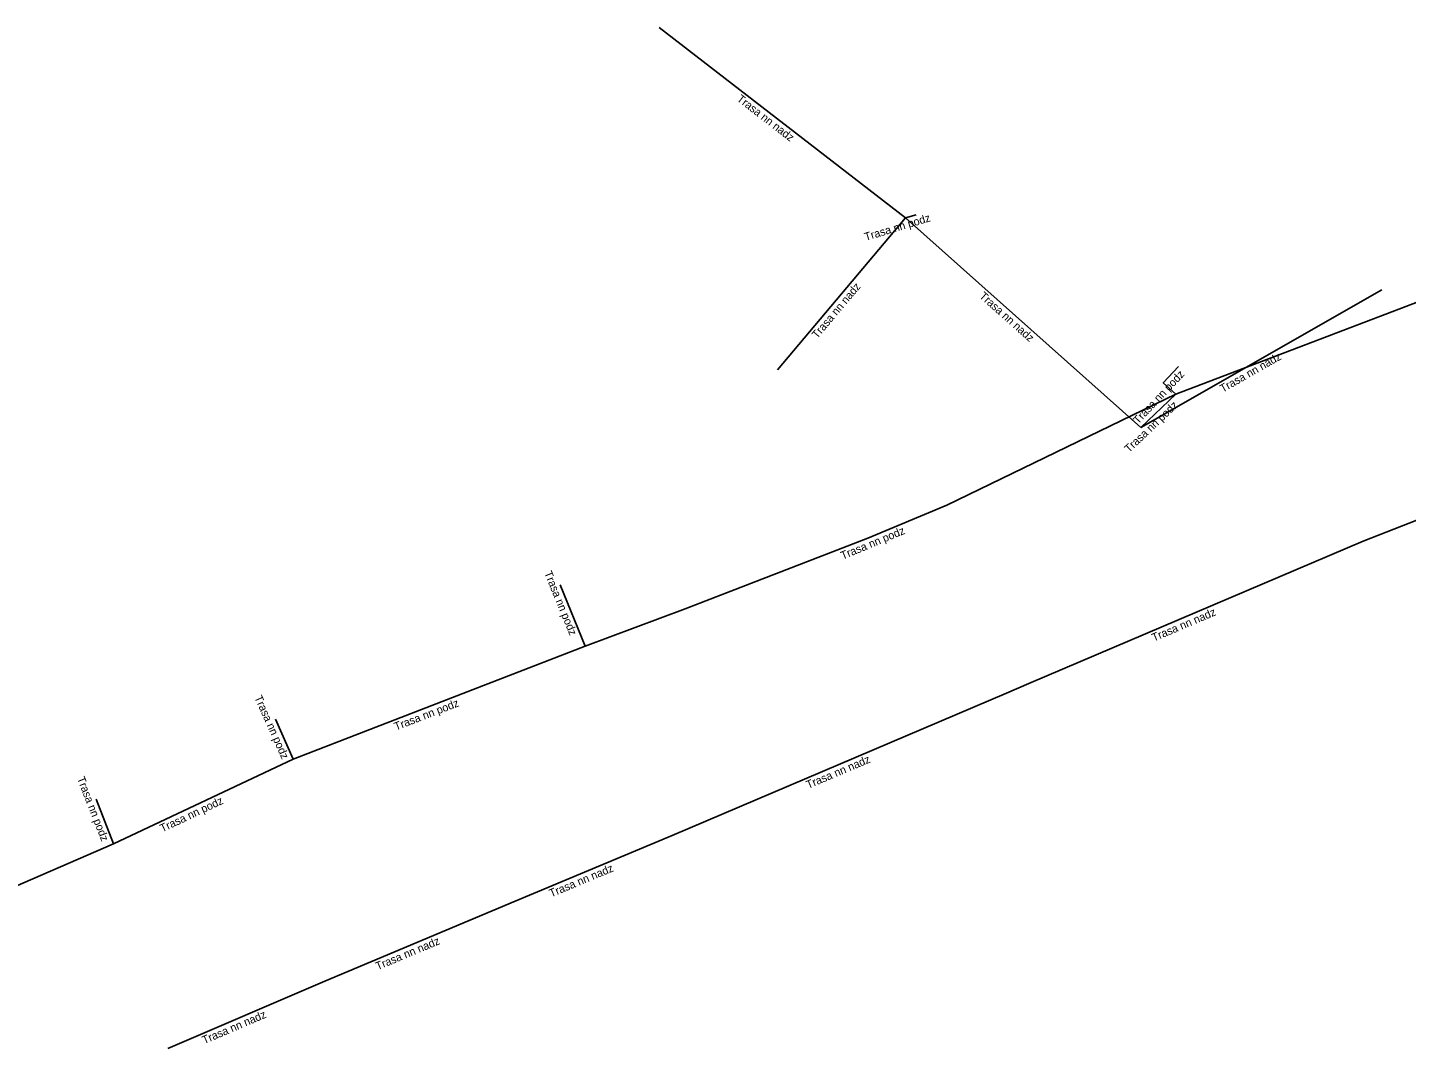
# Model space of a CAD drawing. Extents: x -711262 to -710488, y -1025222 to -1024810.
# Drawn here: x -710787.6 to -710701.4, y -1024944.8 to -1024881 of the extents above; entities that cross this region are included whole.
import ezdxf

# ---------------------------------------------------------------- set-up
doc = ezdxf.new("R2010")
doc.units = 0
doc.layers.add('Popiskový text - Ostatní atributy Trasy', color=7, linetype='Continuous')
doc.layers.add('Spojnice NN', color=7, linetype='Continuous')

msp = doc.modelspace()

# ---------------------------------------------------------------- linework, layer by layer
at = {"layer": 'Spojnice NN'}
for points in [[(-710732.7, -1024892.9), (-710748.1, -1024881)], [(-710663.36, -1024882.83), (-710687.06, -1024892.96), (-710715.81, -1024903.92)], [(-710732.7, -1024892.9), (-710732.04, -1024892.7)], [(-710732.7, -1024892.9), (-710740.7, -1024902.4)], [(-710718, -1024906), (-710732.7, -1024892.9)], [(-710718, -1024906), (-710702.95, -1024897.4)], [(-710715.81, -1024903.92), (-710716.6, -1024903.2), (-710715.64, -1024902.18)], [(-710715.81, -1024903.92), (-710730.12, -1024910.85), (-710735.06, -1024912.9), (-710746.48, -1024917.32), (-710752.72, -1024919.67)], [(-710715.81, -1024903.92), (-710718, -1024906)], [(-710679.3, -1024903.4), (-710704.1, -1024913.1)], [(-710704.1, -1024913.1), (-710725, -1024922)], [(-710752.72, -1024919.67), (-710754.29, -1024915.83)], [(-710752.72, -1024919.67), (-710770.98, -1024926.73)], [(-710725, -1024922), (-710726.4, -1024922.6), (-710747.3, -1024931.5)], [(-710770.98, -1024926.73), (-710772.09, -1024924.23)], [(-710770.98, -1024926.73), (-710782.2, -1024932.02)], [(-710782.2, -1024932.02), (-710783.29, -1024929.22)], [(-710747.3, -1024931.5), (-710757.1, -1024935.6)], [(-710782.2, -1024932.02), (-710801.76, -1024940.5)], [(-710757.1, -1024935.6), (-710769, -1024940.6)], [(-710769, -1024940.6), (-710778.8, -1024944.8)]]:
    msp.add_lwpolyline(points, dxfattribs=at)

# ---------------------------------------------------------------- texts
at = {"layer": 'Popiskový text - Ostatní atributy Trasy'}
for s, rotation, p in [('Trasa nn nadz', 322.30576, (-710743.289, -1024885.54)), ('Trasa nn podz', 16.8584, (-710735.194, -1024894.335)), ('Trasa nn nadz', 49.89909, (-710738.23, -1024900.477)), ('Trasa nn nadz', 318.29396, (-710728.132, -1024897.841)), ('Trasa nn nadz', 29.74488, (-710712.886, -1024903.826)), ('Trasa nn podz', 46.7357, (-710718.17, -1024905.816)), ('Trasa nn podz', 43.52432, (-710718.74, -1024907.599)), ('Trasa nn podz', 22.53746, (-710736.639, -1024914.259)), ('Trasa nn podz', 292.2374, (-710755.298, -1024915.082)), ('Trasa nn nadz', 23.06611, (-710717.191, -1024919.381)), ('Trasa nn podz', 293.94122, (-710773.407, -1024922.867)), ('Trasa nn podz', 21.13837, (-710764.552, -1024924.941)), ('Trasa nn nadz', 23.06611, (-710738.791, -1024928.583)), ('Trasa nn podz', 291.27025, (-710784.493, -1024927.922)), ('Trasa nn podz', 25.24292, (-710779.159, -1024931.305)), ('Trasa nn nadz', 22.70284, (-710754.853, -1024935.364)), ('Trasa nn nadz', 22.79059, (-710765.7, -1024939.919)), ('Trasa nn nadz', 23.19859, (-710776.537, -1024944.538))]:
    msp.add_text(s, height=0.5, rotation=rotation, dxfattribs=at).set_placement(p)

doc.saveas('drawing.dxf')
